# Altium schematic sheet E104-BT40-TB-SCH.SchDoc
size A3
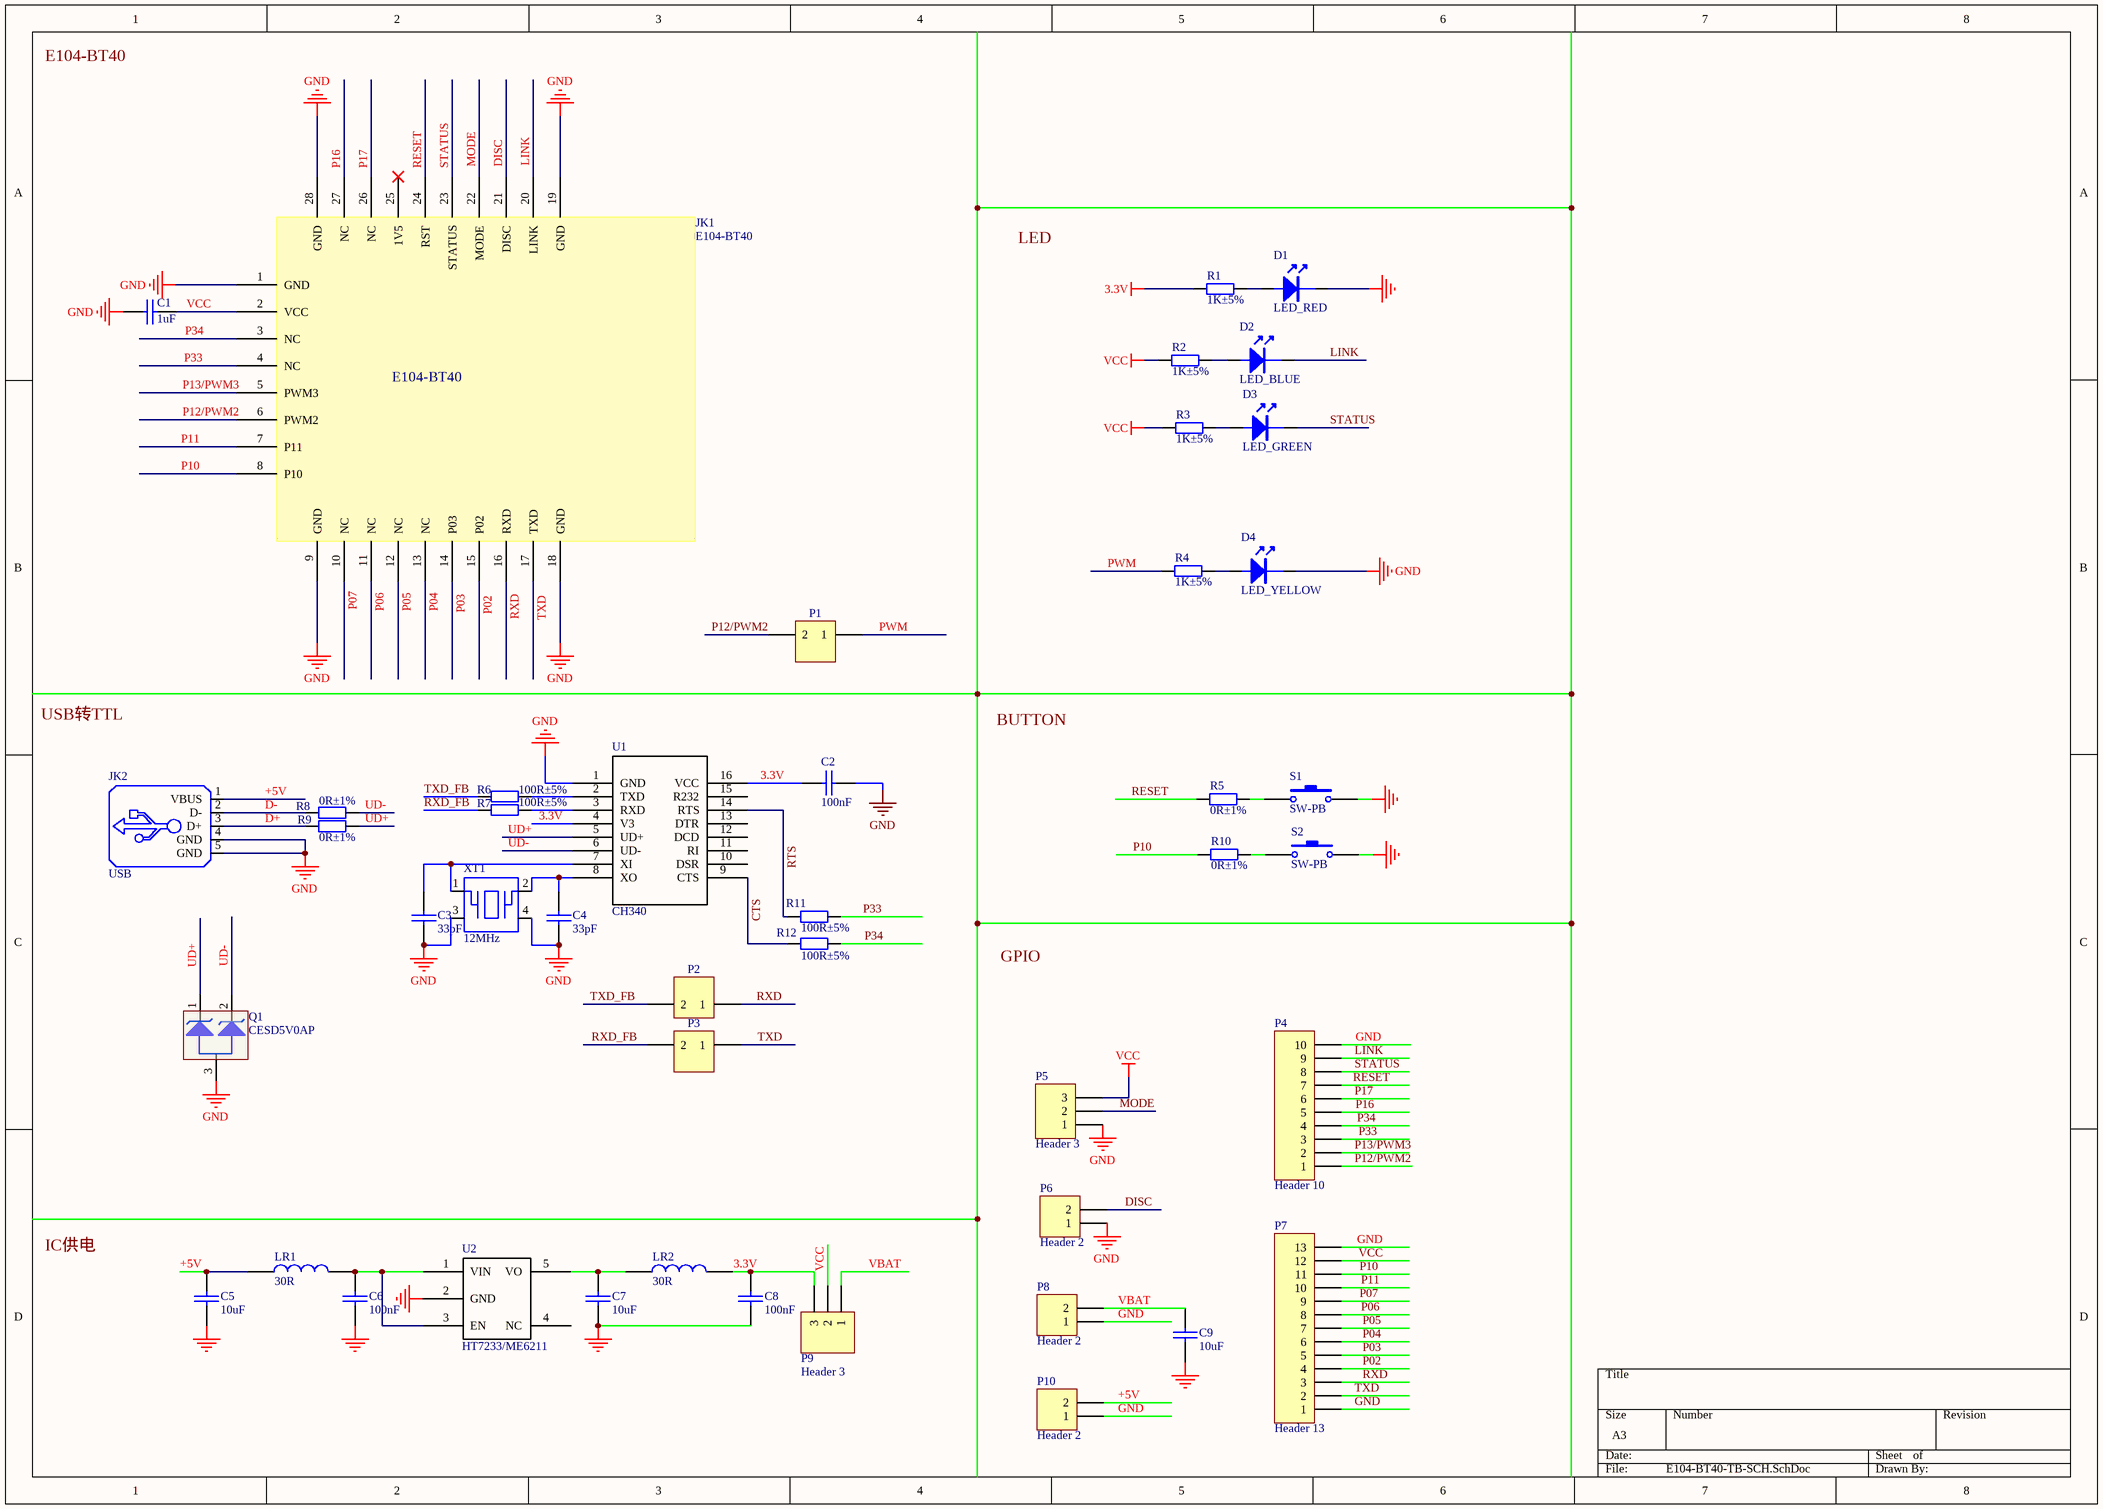
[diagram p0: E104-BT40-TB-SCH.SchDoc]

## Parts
C1  1uF  [E-CAP-0603]
C2  100nF  [E-CAP-0603]
C3  33pF  [E-CAP-0603]
C4  33pF  [E-CAP-0603]
C5  10uF  [E-CAP-0603]
C6  100nF  [E-CAP-0603]
C7  10uF  [E-CAP-0603]
C8  100nF  [E-CAP-0603]
C9  10uF  [E-CAP-0603]
D1  LED_RED  [E-LED-0805]
D2  LED_BLUE  [E-LED-0805]
D3  LED_GREEN  [E-LED-0805]
D4  LED_YELLOW  [E-LED-0805]
JK1  E104-BT40  [E104-BT40]
JK2  USB  [E-USB-AG-DIP]
LR1  30R  [E-IND-0603]
LR2  30R  [E-IND-0603]
P1  Header 2  [HDR1X2]  (value not drawn)
P2  Header 2  [HDR1X2]  (value not drawn)
P3  Header 2  [HDR1X2]  (value not drawn)
P4  Header 10  [HDR1X10]
P5  Header 3  [HDR1X3]
P6  Header 2  [HDR1X2]
P7  Header 13  [HDR1X13]
P8  Header 2  [HDR1X2]
P9  Header 3  [HDR1X3]
P10  Header 2  [HDR1X2]
Q1  CESD5V0AP  [E-SOT-23]
R1  1K±5%  [E-RES-0603]
R2  1K±5%  [E-RES-0603]
R3  1K±5%  [E-RES-0603]
R4  1K±5%  [E-RES-0603]
R5  0R±1%  [E-RES-0603]
R6  100R±5%  [E-RES-0603]
R7  100R±5%  [E-RES-0603]
R8  0R±1%  [E-RES-0603]
R9  0R±1%  [E-RES-0603]
R10  0R±1%  [E-RES-0603]
R11  100R±5%  [E-RES-0603]
R12  100R±5%  [E-RES-0603]
S1  SW-PB  [E-TS3X6X5/2.5]
S2  SW-PB  [E-TS3X6X5/2.5]
U1  CH340  [E-SOP16]
U2  HT7233/ME6211  [E-SOT23-5]
XT1  12MHz  [E-XT3225-4]

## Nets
3.3V: C2.1 C8.1 LR2.2 P9.3 R1.1 U1.4(V3) U1.16(VCC)
GND: C1.1 C2.2 C3.2 C4.2 C5.2 C6.2 C7.2 C8.2 C9.2 D1.K D4.K JK1.1(GND) JK1.9(GND) JK1.18(GND) JK1.19(GND) JK1.28(GND) JK2.4(GND) JK2.5(GND) P4.10 P5.1 P6.1 P7.1 P7.13 P8.1 P10.1 Q1.3 S1.2 S2.2 U1.1(GND) U2.2(GND) XT1.3 XT1.4
VCC: C1.2 JK1.2(VCC) P5.3 P7.12 P9.2 R2.1 R3.1
+5V: C5.1 JK2.1(VBUS) LR1.1 P10.2
CTS: R12.1 U1.9(CTS)
D+: JK2.3(D+) R9.2
D-: JK2.2(D-) R8.2
DISC: JK1.21(DISC) P6.2
LINK: D2.K JK1.20(LINK) P4.9
MODE: JK1.22(MODE) P5.2
P02: JK1.15(P02) P7.4
P03: JK1.14(P03) P7.5
P04: JK1.13(NC) P7.6
P05: JK1.12(NC) P7.7
P06: JK1.11(NC) P7.8
P07: JK1.10(NC) P7.9
P10: JK1.8(P10) P7.11 R10.1
P11: JK1.7(P11) P7.10
P12/PWM2: JK1.6(PWM2) P1.2 P4.1
P13/PWM3: JK1.5(PWM3) P4.2
P16: JK1.27(NC) P4.5
P17: JK1.26(NC) P4.6
P33: JK1.4(NC) P4.3 R11.2
P34: JK1.3(NC) P4.4 R12.2
PWM: P1.1 R4.1
RESET: JK1.24(RST) P4.7 R5.1
RTS: R11.1 U1.14(RTS)
RXD: JK1.16(RXD) P2.1 P7.3
RXD_FB: P3.2 R7.2
STATUS: D3.K JK1.23(STATUS) P4.8
TXD: JK1.17(TXD) P3.1 P7.2
TXD_FB: P2.2 R6.2
UD+: Q1.1 R9.1 U1.5(UD+)
UD-: Q1.2 R8.1 U1.6(UD-)
VBAT: C9.1 P8.2 P9.1
NetC3_1: C3.1 U1.7(XI) XT1.1
NetC4_1: C4.1 U1.8(XO) XT1.2
NetC6_1: C6.1 LR1.2 U2.1(VIN) U2.3(EN)
NetC7_1: C7.1 LR2.1 U2.5(VO)
NetD1_A: D1.A R1.2
NetD2_A: D2.A R2.2
NetD3_A: D3.A R3.2
NetD4_A: D4.A R4.2
NetR5_2: R5.2 S1.1
NetR6_1: R6.1 U1.2(TXD)
NetR7_1: R7.1 U1.3(RXD)
NetR10_2: R10.2 S2.1

Not connected (* = marked no-connect by the designer): JK1 25(1V5)*; U1 10(DSR) 11(RI) 12(DCD) 13(DTR) 15(R232); U2 4(NC)

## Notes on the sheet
- E104-BT40
- LED
- USB转TTL
- BUTTON
- GPIO
- IC供电

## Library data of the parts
C1-C9 = C: Capacitor
D1-D4 = LED
LR1 LR2 = L: Inductor
P1-P3 P6 P8 P10 = Header 2: Header, 2-Pin
P4 = Header 10: Header, 10-Pin
P5 P9 = Header 3: Header, 3-Pin
P7 = Header 13: Header, 13-Pin
Q1 = 双TVS-共阳
R1-R12 = R: Resistor
S1 S2 = SW-PB: Switch
U1 = CH340G
XT1 = XT-SMD1: XTAL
